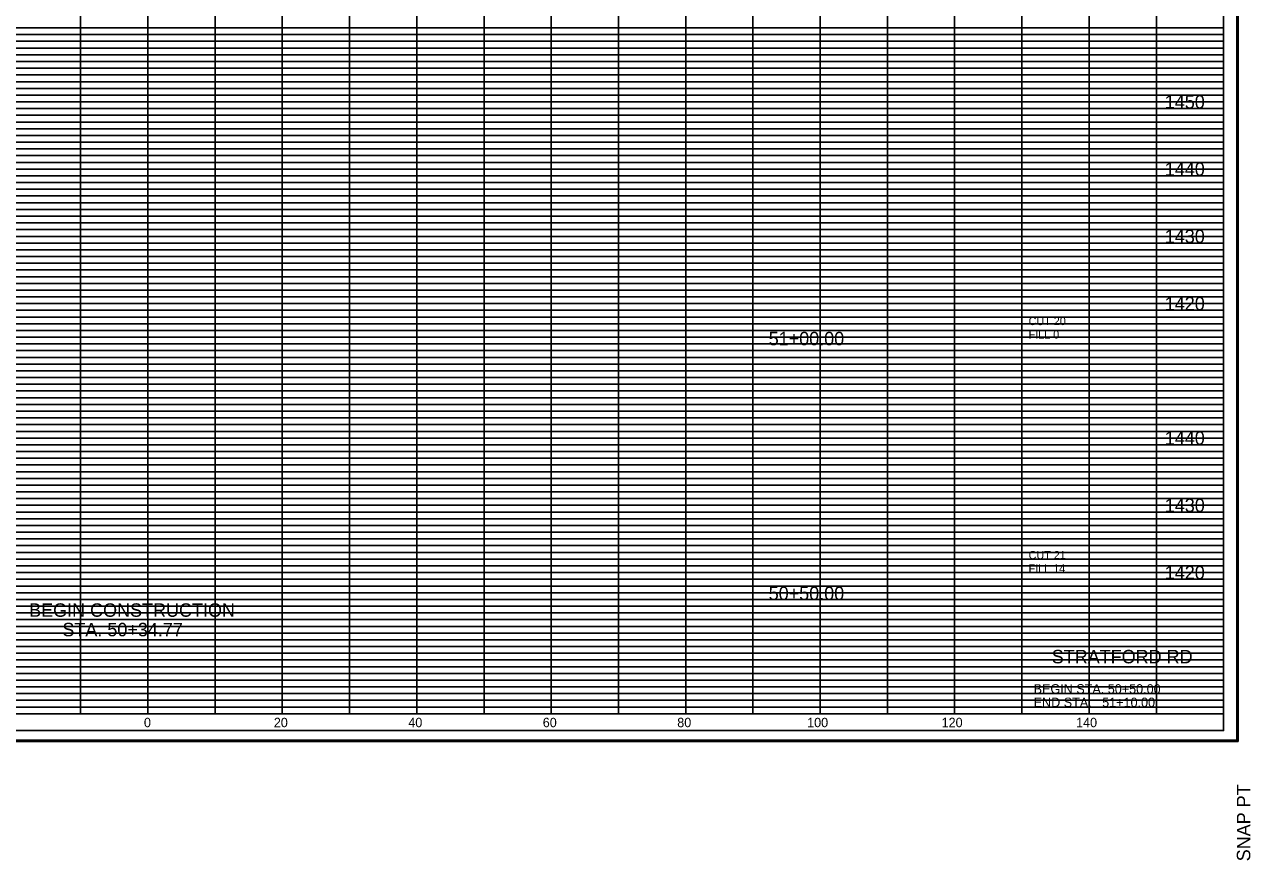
# Model space of a CAD drawing. Extents: x 980 to 1324, y 978 to 1227.
# Drawn here: x 1141.7 to 1324, y 978.2 to 1102.5 of the extents above; entities that cross this region are included whole.
import ezdxf

# ---------------------------------------------------------------- set-up
doc = ezdxf.new("R2010")
doc.units = 0
for name, color, linetype in [('DESIGN - SHEET - Corner Text', 7, 'Continuous'), ('DESIGN - SHEET - Light Grid', 7, 'Continuous'), ('DESIGN - SHEET - Linework', 7, 'Continuous'), ('DESIGN - SHEET - Plot Shape', 7, 'Continuous'), ('DESIGN - TYPICAL - Finished Grade and Subgrade', 7, 'Continuous'), ('DESIGN - TYPICAL - Text', 7, 'Continuous')]:
    doc.layers.add(name, color=color, linetype=linetype)

# ---------------------------------------------------------------- blocks, each defined once
blk = doc.blocks.new('XSTSHT')
at = {"layer": 'DESIGN - SHEET - Light Grid'}
for p, q in [((8, 10.2), (16, 10.2)), ((8, 10.1), (16, 10.1)), ((16, 10.2), (24, 10.2)), ((16, 10.1), (24, 10.1)), ((24, 10.2), (32, 10.2)), ((24, 10.1), (32, 10.1)), ((8, 9.9), (16, 9.9)), ((16, 9.9), (24, 9.9)), ((24, 9.9), (32, 9.9)), ((8, 9.8), (16, 9.8)), ((8, 9.7), (16, 9.7)), ((16, 9.8), (24, 9.8)), ((16, 9.7), (24, 9.7)), ((24, 9.8), (32, 9.8)), ((24, 9.7), (32, 9.7)), ((8, 9.6), (16, 9.6)), ((8, 9.5), (16, 9.5)), ((16, 9.6), (24, 9.6)), ((16, 9.5), (24, 9.5)), ((24, 9.6), (32, 9.6)), ((24, 9.5), (32, 9.5)), ((8, 9.4), (16, 9.4)), ((8, 9.3), (16, 9.3)), ((16, 9.4), (24, 9.4)), ((16, 9.3), (24, 9.3)), ((24, 9.4), (32, 9.4)), ((24, 9.3), (32, 9.3)), ((8, 9.2), (16, 9.2)), ((16, 9.2), (24, 9.2)), ((24, 9.2), (32, 9.2)), ((8, 9.1), (16, 9.1)), ((16, 9.1), (24, 9.1)), ((24, 9.1), (32, 9.1)), ((8, 8.9), (16, 8.9)), ((8, 8.8), (16, 8.8)), ((16, 8.9), (24, 8.9)), ((16, 8.8), (24, 8.8)), ((24, 8.9), (32, 8.9)), ((24, 8.8), (32, 8.8)), ((8, 8.7), (16, 8.7)), ((8, 8.6), (16, 8.6)), ((16, 8.7), (24, 8.7)), ((16, 8.6), (24, 8.6)), ((24, 8.7), (32, 8.7)), ((24, 8.6), (32, 8.6)), ((8, 8.5), (16, 8.5)), ((8, 8.4), (16, 8.4)), ((16, 8.5), (24, 8.5)), ((16, 8.4), (24, 8.4)), ((24, 8.5), (32, 8.5)), ((24, 8.4), (32, 8.4)), ((8, 8.3), (16, 8.3)), ((16, 8.3), (24, 8.3)), ((24, 8.3), (32, 8.3)), ((8, 8.2), (16, 8.2)), ((8, 8.1), (16, 8.1)), ((16, 8.2), (24, 8.2)), ((16, 8.1), (24, 8.1)), ((24, 8.2), (32, 8.2)), ((24, 8.1), (32, 8.1)), ((8, 7.9), (16, 7.9)), ((16, 7.9), (24, 7.9)), ((24, 7.9), (32, 7.9)), ((8, 7.8), (16, 7.8)), ((8, 7.7), (16, 7.7)), ((16, 7.8), (24, 7.8)), ((16, 7.7), (24, 7.7)), ((24, 7.8), (32, 7.8)), ((24, 7.7), (32, 7.7)), ((8, 7.6), (16, 7.6)), ((8, 7.5), (16, 7.5)), ((16, 7.6), (24, 7.6)), ((16, 7.5), (24, 7.5)), ((24, 7.6), (32, 7.6)), ((24, 7.5), (32, 7.5)), ((8, 7.4), (16, 7.4)), ((8, 7.3), (16, 7.3)), ((16, 7.4), (24, 7.4)), ((16, 7.3), (24, 7.3)), ((24, 7.4), (32, 7.4)), ((24, 7.3), (32, 7.3)), ((8, 7.2), (16, 7.2)), ((16, 7.2), (24, 7.2)), ((24, 7.2), (32, 7.2)), ((8, 7.1), (16, 7.1)), ((16, 7.1), (24, 7.1)), ((24, 7.1), (32, 7.1)), ((8, 6.9), (16, 6.9)), ((8, 6.8), (16, 6.8)), ((16, 6.9), (24, 6.9)), ((16, 6.8), (24, 6.8)), ((24, 6.9), (32, 6.9)), ((24, 6.8), (32, 6.8)), ((8, 6.7), (16, 6.7)), ((8, 6.6), (16, 6.6)), ((16, 6.7), (24, 6.7)), ((16, 6.6), (24, 6.6)), ((24, 6.7), (32, 6.7)), ((24, 6.6), (32, 6.6)), ((8, 6.5), (16, 6.5)), ((8, 6.4), (16, 6.4)), ((16, 6.5), (24, 6.5)), ((16, 6.4), (24, 6.4)), ((24, 6.5), (32, 6.5)), ((24, 6.4), (32, 6.4)), ((8, 6.3), (16, 6.3)), ((8, 6.2), (16, 6.2)), ((16, 6.3), (24, 6.3)), ((16, 6.2), (24, 6.2)), ((24, 6.3), (32, 6.3)), ((24, 6.2), (32, 6.2)), ((8, 6.1), (16, 6.1)), ((16, 6.1), (24, 6.1)), ((24, 6.1), (32, 6.1)), ((8, 5.9), (16, 5.9)), ((16, 5.9), (24, 5.9)), ((24, 5.9), (32, 5.9)), ((8, 5.8), (16, 5.8)), ((8, 5.7), (16, 5.7)), ((16, 5.8), (24, 5.8)), ((16, 5.7), (24, 5.7)), ((24, 5.8), (32, 5.8)), ((24, 5.7), (32, 5.7)), ((8, 5.6), (16, 5.6)), ((8, 5.5), (16, 5.5)), ((16, 5.6), (24, 5.6)), ((16, 5.5), (24, 5.5)), ((24, 5.6), (32, 5.6)), ((24, 5.5), (32, 5.5)), ((8, 5.4), (16, 5.4)), ((8, 5.3), (16, 5.3)), ((16, 5.4), (24, 5.4)), ((16, 5.3), (24, 5.3)), ((24, 5.4), (32, 5.4)), ((24, 5.3), (32, 5.3)), ((8, 5.2), (16, 5.2)), ((16, 5.2), (24, 5.2)), ((24, 5.2), (32, 5.2)), ((8, 5.1), (16, 5.1)), ((16, 5.1), (24, 5.1)), ((24, 5.1), (32, 5.1)), ((8, 4.9), (16, 4.9)), ((8, 4.8), (16, 4.8)), ((16, 4.9), (24, 4.9)), ((16, 4.8), (24, 4.8)), ((24, 4.9), (32, 4.9)), ((24, 4.8), (32, 4.8)), ((8, 4.7), (16, 4.7)), ((8, 4.6), (16, 4.6)), ((16, 4.7), (24, 4.7)), ((16, 4.6), (24, 4.6)), ((24, 4.7), (32, 4.7)), ((24, 4.6), (32, 4.6)), ((8, 4.5), (16, 4.5)), ((8, 4.4), (16, 4.4)), ((16, 4.5), (24, 4.5)), ((16, 4.4), (24, 4.4)), ((24, 4.5), (32, 4.5)), ((24, 4.4), (32, 4.4)), ((8, 4.3), (16, 4.3)), ((8, 4.2), (16, 4.2)), ((16, 4.3), (24, 4.3)), ((16, 4.2), (24, 4.2)), ((24, 4.3), (32, 4.3)), ((24, 4.2), (32, 4.2)), ((8, 4.1), (16, 4.1)), ((16, 4.1), (24, 4.1)), ((24, 4.1), (32, 4.1)), ((8, 3.9), (16, 3.9)), ((16, 3.9), (24, 3.9)), ((24, 3.9), (32, 3.9)), ((8, 3.8), (16, 3.8)), ((8, 3.7), (16, 3.7)), ((16, 3.8), (24, 3.8)), ((16, 3.7), (24, 3.7)), ((24, 3.8), (32, 3.8)), ((24, 3.7), (32, 3.7)), ((8, 3.6), (16, 3.6)), ((8, 3.5), (16, 3.5)), ((16, 3.6), (24, 3.6)), ((16, 3.5), (24, 3.5)), ((24, 3.6), (32, 3.6)), ((24, 3.5), (32, 3.5)), ((8, 3.4), (16, 3.4)), ((8, 3.3), (16, 3.3)), ((16, 3.4), (24, 3.4)), ((16, 3.3), (24, 3.3)), ((24, 3.4), (32, 3.4)), ((24, 3.3), (32, 3.3)), ((8, 3.2), (16, 3.2)), ((8, 3.1), (16, 3.1)), ((16, 3.2), (24, 3.2)), ((16, 3.1), (24, 3.1)), ((24, 3.2), (32, 3.2)), ((24, 3.1), (32, 3.1)), ((8, 2.9), (16, 2.9)), ((8, 2.8), (16, 2.8)), ((16, 2.9), (24, 2.9)), ((16, 2.8), (24, 2.8)), ((24, 2.9), (32, 2.9)), ((24, 2.8), (32, 2.8)), ((8, 2.7), (16, 2.7)), ((8, 2.6), (16, 2.6)), ((16, 2.7), (24, 2.7)), ((16, 2.6), (24, 2.6)), ((24, 2.7), (32, 2.7)), ((24, 2.6), (32, 2.6)), ((8, 2.5), (16, 2.5)), ((8, 2.4), (16, 2.4)), ((16, 2.5), (24, 2.5)), ((16, 2.4), (24, 2.4)), ((24, 2.5), (32, 2.5)), ((24, 2.4), (32, 2.4)), ((8, 2.3), (16, 2.3)), ((8, 2.2), (16, 2.2)), ((16, 2.3), (24, 2.3)), ((16, 2.2), (24, 2.2)), ((24, 2.3), (32, 2.3)), ((24, 2.2), (32, 2.2)), ((8, 2.1), (16, 2.1)), ((16, 2.1), (24, 2.1)), ((24, 2.1), (32, 2.1)), ((8, 1.9), (16, 1.9)), ((16, 1.9), (24, 1.9)), ((24, 1.9), (32, 1.9)), ((8, 1.8), (16, 1.8)), ((8, 1.7), (16, 1.7)), ((16, 1.8), (24, 1.8)), ((16, 1.7), (24, 1.7)), ((24, 1.8), (32, 1.8)), ((24, 1.7), (32, 1.7)), ((8, 1.6), (16, 1.6)), ((8, 1.5), (16, 1.5)), ((16, 1.6), (24, 1.6)), ((16, 1.5), (24, 1.5)), ((24, 1.6), (32, 1.6)), ((24, 1.5), (32, 1.5)), ((8, 1.4), (16, 1.4)), ((8, 1.3), (16, 1.3)), ((16, 1.4), (24, 1.4)), ((16, 1.3), (24, 1.3)), ((24, 1.4), (32, 1.4)), ((24, 1.3), (32, 1.3)), ((8, 1.2), (16, 1.2)), ((8, 1.1), (16, 1.1)), ((16, 1.2), (24, 1.2)), ((16, 1.1), (24, 1.1)), ((24, 1.2), (32, 1.2)), ((24, 1.1), (32, 1.1)), ((8, 0.9), (16, 0.9)), ((8, 0.8), (16, 0.8)), ((16, 0.9), (24, 0.9)), ((16, 0.8), (24, 0.8)), ((24, 0.9), (32, 0.9)), ((24, 0.8), (32, 0.8)), ((8, 0.7), (16, 0.7)), ((8, 0.6), (16, 0.6)), ((16, 0.7), (24, 0.7)), ((16, 0.6), (24, 0.6)), ((24, 0.7), (32, 0.7)), ((24, 0.6), (32, 0.6)), ((8, 0.5), (16, 0.5)), ((8, 0.4), (16, 0.4)), ((16, 0.5), (24, 0.5)), ((16, 0.4), (24, 0.4)), ((24, 0.5), (32, 0.5)), ((24, 0.4), (32, 0.4)), ((8, 0.3), (16, 0.3)), ((8, 0.2), (16, 0.2)), ((16, 0.3), (24, 0.3)), ((16, 0.2), (24, 0.2)), ((24, 0.3), (32, 0.3)), ((24, 0.2), (32, 0.2)), ((8, 0.1), (16, 0.1)), ((16, 0.1), (24, 0.1)), ((24, 0.1), (32, 0.1))]:
    blk.add_line(p, q, dxfattribs=at)
at = {"layer": 'DESIGN - SHEET - Linework'}
for p, q in [((32.217, 21.414), (32.217, -0.414)), ((15, 0), (15, 21)), ((16, 0), (16, 21)), ((17, 0), (17, 21)), ((18, 0), (18, 21)), ((19, 0), (19, 21)), ((20, 0), (20, 21)), ((21, 0), (21, 21)), ((22, 0), (22, 21)), ((23, 0), (23, 21)), ((24, 0), (24, 21)), ((25, 0), (25, 21)), ((26, 0), (26, 21)), ((27, 0), (27, 21)), ((28, 0), (28, 20)), ((29, 0), (29, 20)), ((30, 0), (30, 20)), ((31, 0), (31, 20)), ((0, 10), (32, 10)), ((0, 9), (32, 9)), ((0, 8), (32, 8)), ((0, 7), (32, 7)), ((0, 6), (32, 6)), ((0, 5), (32, 5)), ((0, 4), (32, 4)), ((0, 3), (32, 3)), ((0, 2), (32, 2)), ((0, 1), (32, 1)), ((-1.823, -0.414), (32.217, -0.414))]:
    blk.add_line(p, q, dxfattribs=at)
blk.add_lwpolyline([(0, 21), (0, 0), (32, 0), (32, 21), (0, 21)], dxfattribs=at)
at = {"layer": 'DESIGN - SHEET - Plot Shape'}
for points in [[(-1.803, 21.394), (32.197, 21.394), (32.197, -0.394), (-1.803, -0.394)], [(-0.85, 21), (32, 21), (32, -0.25), (-0.85, -0.25)]]:
    blk.add_lwpolyline(points, close=True, dxfattribs=at)
at = {"layer": 'DESIGN - SHEET - Corner Text'}
blk.add_text('SNAP PT  ', height=0.2, rotation=90, dxfattribs=at).set_placement((32.397, -2.194))

msp = doc.modelspace()

# ---------------------------------------------------------------- linework, layer by layer
at = {"layer": 'DESIGN - SHEET - Plot Shape'}
msp.add_lwpolyline([(991.5, 997.5), (1320, 997.5), (1320, 1210), (991.5, 1210)], close=True, dxfattribs=at)

# ---------------------------------------------------------------- block references
at = {"layer": 'DESIGN - TYPICAL - Finished Grade and Subgrade', "xscale": 10, "yscale": 10}
msp.add_blockref('XSTSHT', (1000, 1000), dxfattribs=at)

# ---------------------------------------------------------------- texts
at = {"layer": 'DESIGN - SHEET - Corner Text'}
for s, height, p in [('1450', 2, (1311.25, 1090)), ('1440', 2, (1311.25, 1080)), ('1430', 2, (1311.25, 1070)), ('1420', 2, (1311.25, 1060)), ('51+00.00', 2, (1252.34, 1054.8)), ('1440', 2, (1311.25, 1040)), ('1430', 2, (1311.25, 1030)), ('1420', 2, (1311.25, 1020)), ('50+50.00', 2, (1252.34, 1016.91)), ('STRATFORD RD', 2, (1294.44, 1007.5)), ('BEGIN STA. 50+50.00', 1.4, (1291.75, 1003)), ('END STA.   51+10.00', 1.4, (1291.75, 1001)), ('0', 1.4, (1159.42, 998)), ('0', 1.4, (1159.42, 998)), ('20', 1.4, (1178.74, 998)), ('40', 1.4, (1198.74, 998)), ('60', 1.4, (1218.74, 998)), ('80', 1.4, (1238.74, 998)), ('100', 1.4, (1258.06, 998)), ('120', 1.4, (1278.06, 998)), ('140', 1.4, (1298.06, 998))]:
    msp.add_text(s, height=height, dxfattribs=at).set_placement(p)
at = {"layer": 'DESIGN - TYPICAL - Text'}
for s, height, p in [('CUT 20', 1.2, (1291, 1057.8)), ('FILL 0', 1.2, (1291, 1055.8)), ('CUT 21', 1.2, (1291, 1023.01)), ('FILL 14', 1.2, (1291, 1021.01)), ('BEGIN CONSTRUCTION', 2, (1142.35, 1014.42)), ('STA. 50+34.77', 2, (1147.29, 1011.52))]:
    msp.add_text(s, height=height, dxfattribs=at).set_placement(p)

doc.saveas('drawing.dxf')
